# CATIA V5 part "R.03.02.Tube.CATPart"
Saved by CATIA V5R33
Part number: R.03.02.Tube
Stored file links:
  C:\Users\Ryzen5700u\Desktop\robot_cicloidale_singolo\Assieme_robot_cicloidale_singolo\R.03.02.Tube.CATPart

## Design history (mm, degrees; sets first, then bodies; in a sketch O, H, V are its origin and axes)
Body1 "Solid1" (main body)
  Solid1: solid without history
